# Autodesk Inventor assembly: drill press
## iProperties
Author: Elise Moss
Created: 2001-09
Part Number: drill press
Document SubType Name: Assembly
Designer: Elise Moss
Control State: 0
Master: False
Checked Out: False
PropertySet Name: Design Tracking Control
Length Units: 11272
Angle Units: 11279
Time Units: 11290
Mass Units: 11286
Shininess: 3
Angle Display Precision: 2
Document Length Units: 11272
Document Angle Units: 11286
Document Time Units: 11279
Document Mass Units: 11290
Document Length Units Precision: 3
Document Angle Units Precision: 2
Compacted: False
PropertySet Name: _Private Model Information
Density: 0.0
Volumn: 0.0
Area: 0.0
PropertySet Name: Model Information
